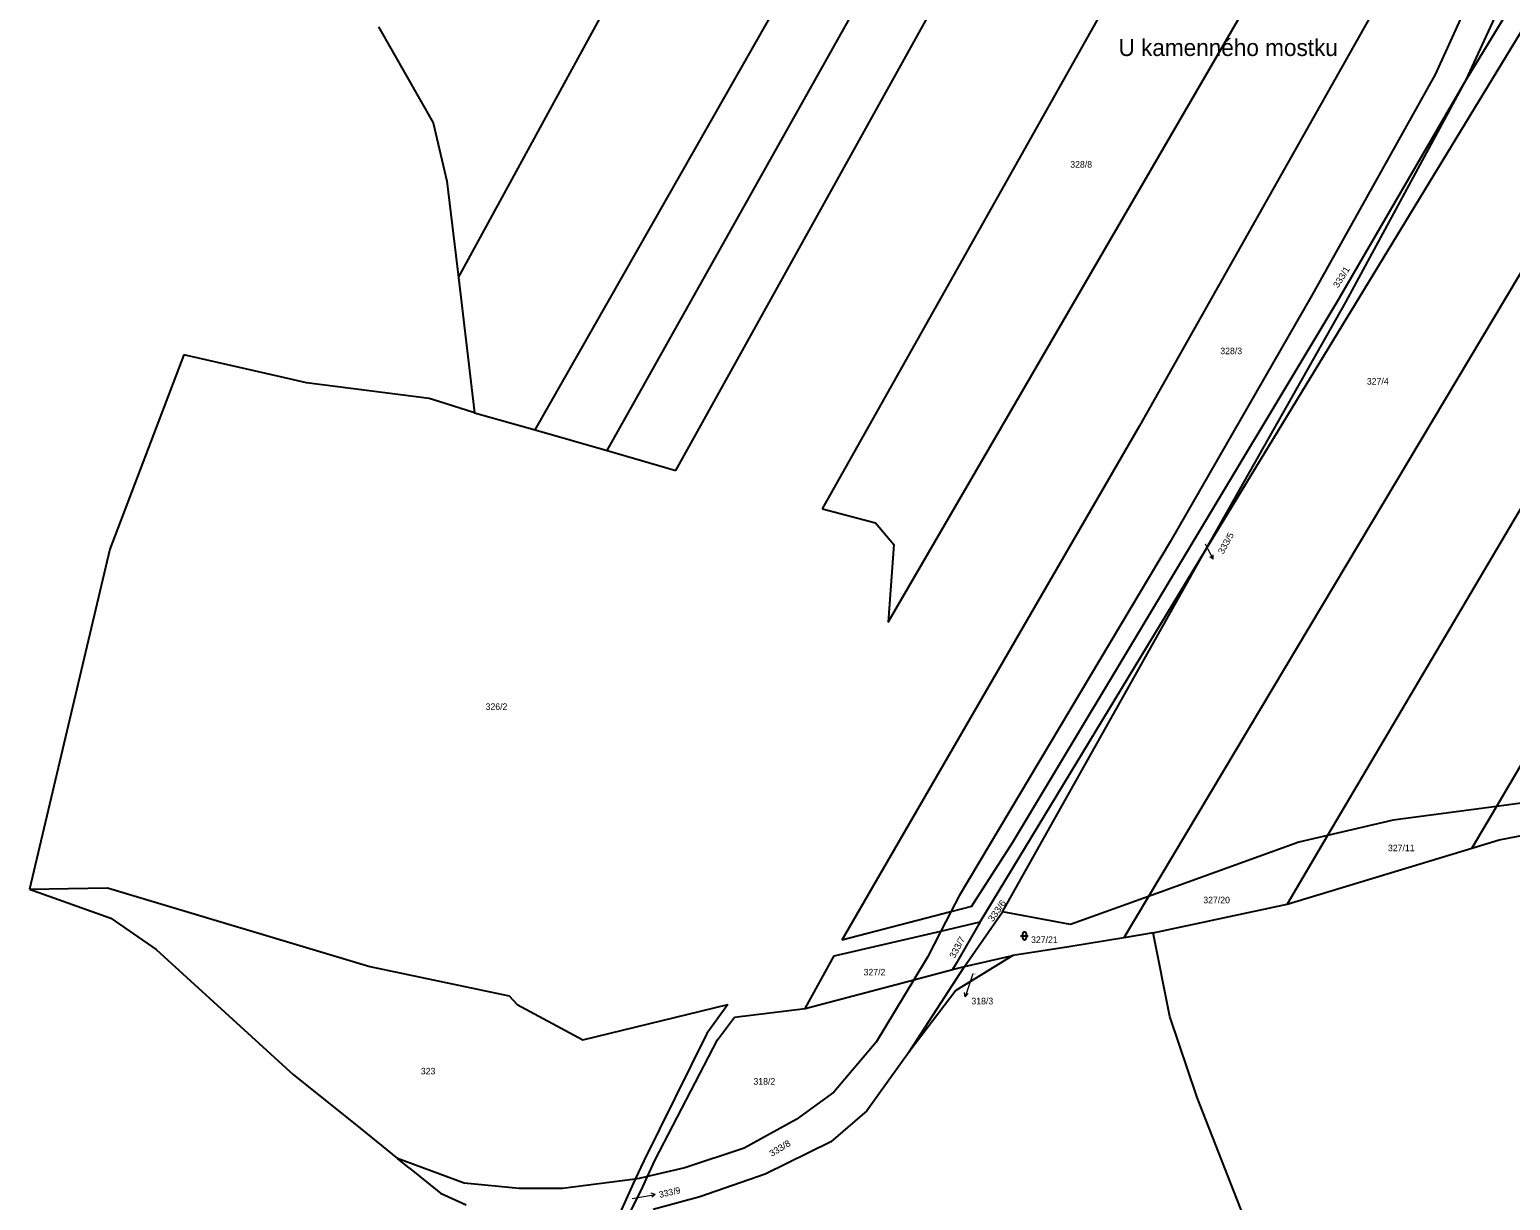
# Model space of a CAD drawing. Extents: x -645290 to -643454, y -1064771 to -1062356.
# Drawn here: x -645018.5 to -644632.1, y -1064454.7 to -1064149.2 of the extents above; entities that cross this region are included whole.
import ezdxf
from ezdxf.enums import TextEntityAlignment as Align

# ---------------------------------------------------------------- set-up
doc = ezdxf.new("R2010")
doc.units = 0
doc.header["$LTSCALE"] = 0.68
for name, color, linetype, lineweight in [('1', 7, 'Continuous', 25), ('3', 7, 'Continuous', 25), ('7', 7, 'Continuous', 13)]:
    doc.layers.add(name, color=color, linetype=linetype, lineweight=lineweight)
doc.layers.add('2', color=7, linetype='Continuous')

msp = doc.modelspace()

# ---------------------------------------------------------------- linework, layer by layer
at = {"layer": '1'}
for p, q in [((-644906.52, -1064213.87), (-644783.89, -1063988.5)), ((-644886.54, -1064253.68), (-644757.8, -1064027.45)), ((-644867.77, -1064259.04), (-644738.28, -1064028.29)), ((-644849.89, -1064264.24), (-644718.76, -1064028.29)), ((-644811.6, -1064274.24), (-644680.91, -1064041.96)), ((-644794.48, -1064303.81), (-644654.09, -1064062.28)), ((-644633.09, -1064082.79), (-644728.84, -1064252.56)), ((-644566.05, -1064106.42), (-644726.5, -1064375.38)), ((-644643.64, -1064162.33), (-644616.86, -1064118.44)), ((-644711.6, -1064285.03), (-644613.22, -1064123.4)), ((-644542.91, -1064127.64), (-644679.8, -1064359.5)), ((-644640.85, -1064137.12), (-644651.74, -1064160.97)), ((-644643.64, -1064162.33), (-644632.24, -1064137.78)), ((-644927.45, -1064148.47), (-644913.14, -1064173.54)), ((-644517.28, -1064150.01), (-644635.73, -1064351.92)), ((-644651.74, -1064160.97), (-644683.79, -1064218.41)), ((-644677.23, -1064220.22), (-644643.64, -1064162.33)), ((-644675.04, -1064220.36), (-644643.64, -1064162.33)), ((-644913.14, -1064173.54), (-644909.57, -1064188.75)), ((-644909.57, -1064188.75), (-644906.52, -1064213.87)), ((-644906.52, -1064213.87), (-644902.35, -1064249.17)), ((-644683.79, -1064218.41), (-644720.83, -1064282.9)), ((-644761.87, -1064361.2), (-644677.23, -1064220.22)), ((-644711.6, -1064285.03), (-644675.04, -1064220.36)), ((-644978.2, -1064234.1), (-644997.51, -1064284.77)), ((-644953.05, -1064239.85), (-644978.2, -1064234.1)), ((-644946.22, -1064241.41), (-644953.05, -1064239.85)), ((-644914.25, -1064245.46), (-644946.22, -1064241.41)), ((-644911.67, -1064246.25), (-644914.25, -1064245.46)), ((-644902.35, -1064249.17), (-644911.67, -1064246.25)), ((-644902.35, -1064249.17), (-644886.54, -1064253.68)), ((-644728.84, -1064252.56), (-644806.55, -1064386.79)), ((-644886.54, -1064253.68), (-644867.77, -1064259.04)), ((-644867.77, -1064259.04), (-644849.89, -1064264.24)), ((-644811.6, -1064274.24), (-644797.78, -1064277.9)), ((-644797.78, -1064277.9), (-644792.98, -1064283.53)), ((-644792.98, -1064283.53), (-644794.48, -1064303.81)), ((-644720.83, -1064282.9), (-644775.91, -1064375.21)), ((-644997.51, -1064284.77), (-645018.48, -1064373.48)), ((-644770.4, -1064382.02), (-644711.6, -1064285.03)), ((-644764.58, -1064379.41), (-644711.6, -1064285.03)), ((-644635.73, -1064351.92), (-644662.62, -1064355.51)), ((-644635.73, -1064351.92), (-644642.1, -1064362.78)), ((-644627.97, -1064350.89), (-644635.73, -1064351.92)), ((-644662.62, -1064355.51), (-644679.8, -1064359.5)), ((-644635.04, -1064360.64), (-644610.32, -1064355.76)), ((-644772.68, -1064377.95), (-644761.87, -1064361.2)), ((-644687.24, -1064361.23), (-644726.5, -1064375.38)), ((-644679.8, -1064359.5), (-644690.36, -1064377.39)), ((-644679.8, -1064359.5), (-644687.24, -1064361.23)), ((-644642.1, -1064362.78), (-644635.04, -1064360.64)), ((-644690.36, -1064377.39), (-644642.1, -1064362.78)), ((-645018.48, -1064373.48), (-644998.19, -1064373.1)), ((-644998.19, -1064373.1), (-644929.72, -1064393.66)), ((-645018.48, -1064373.48), (-644997.3, -1064381.02)), ((-644775.91, -1064375.21), (-644778.06, -1064379.35)), ((-644726.5, -1064375.38), (-644746.85, -1064382.72)), ((-644726.5, -1064375.38), (-644732.91, -1064386.13)), ((-644778.06, -1064379.35), (-644806.55, -1064386.79)), ((-644778.06, -1064379.35), (-644780.67, -1064384.39)), ((-644772.68, -1064377.95), (-644778.06, -1064379.35)), ((-644774.56, -1064393.62), (-644764.58, -1064379.41)), ((-644746.85, -1064382.72), (-644764.58, -1064379.41)), ((-644725.25, -1064384.85), (-644690.36, -1064377.39)), ((-644997.3, -1064381.02), (-644985.45, -1064389.22)), ((-644808.52, -1064390.83), (-644780.67, -1064384.39)), ((-644780.67, -1064384.39), (-644784.21, -1064391.22)), ((-644780.67, -1064384.39), (-644770.4, -1064382.02)), ((-644770.4, -1064382.02), (-644776.94, -1064393.3)), ((-644747.33, -1064388.55), (-644761.89, -1064390.79)), ((-644732.91, -1064386.13), (-644747.33, -1064388.55)), ((-644725.25, -1064384.85), (-644732.91, -1064386.13)), ((-644720.96, -1064406.66), (-644725.25, -1064384.85)), ((-644985.45, -1064389.22), (-644949.61, -1064421.91)), ((-644816.08, -1064404.6), (-644808.52, -1064390.83)), ((-644784.21, -1064391.22), (-644787.76, -1064397.11)), ((-644761.89, -1064390.79), (-644776.79, -1064399.91)), ((-644774.56, -1064393.62), (-644761.89, -1064390.79)), ((-644929.72, -1064393.66), (-644893.37, -1064401.26)), ((-644788.97, -1064415.93), (-644774.56, -1064393.62)), ((-644787.76, -1064397.11), (-644777.68, -1064394.45)), ((-644776.94, -1064393.3), (-644777.68, -1064394.45)), ((-644777.68, -1064394.45), (-644774.56, -1064393.62)), ((-644816.08, -1064404.6), (-644787.76, -1064397.11)), ((-644787.76, -1064397.11), (-644797.53, -1064413.35)), ((-644776.79, -1064399.91), (-644788.97, -1064415.93)), ((-644893.37, -1064401.26), (-644891.27, -1064403.52)), ((-644891.27, -1064403.52), (-644874.15, -1064412.81)), ((-644874.15, -1064412.81), (-644836.31, -1064403.52)), ((-644836.31, -1064403.52), (-644841.72, -1064411.12)), ((-644839.01, -1064412.81), (-644834.51, -1064406.89)), ((-644834.51, -1064406.89), (-644816.08, -1064404.6)), ((-644713.81, -1064427.79), (-644720.96, -1064406.66)), ((-644841.72, -1064411.12), (-644858.24, -1064444.35)), ((-644855.23, -1064444.06), (-644839.01, -1064412.81)), ((-644797.53, -1064413.35), (-644808.62, -1064426.46)), ((-644788.97, -1064415.93), (-644800.01, -1064431.32)), ((-644949.61, -1064421.91), (-644933.65, -1064434.67)), ((-644808.62, -1064426.46), (-644818.45, -1064433.58)), ((-644700.13, -1064462.71), (-644713.81, -1064427.79)), ((-644933.65, -1064434.67), (-644922.5, -1064443.69)), ((-644818.45, -1064433.58), (-644832.06, -1064441)), ((-644800.01, -1064431.32), (-644809.36, -1064439.35)), ((-644832.06, -1064441), (-644847.52, -1064446.17)), ((-644809.36, -1064439.35), (-644826.55, -1064447.8)), ((-644919.32, -1064446.26), (-644922.5, -1064443.69)), ((-644905.1, -1064450.2), (-644922.5, -1064443.69)), ((-644919.32, -1064446.26), (-644911.29, -1064452.76)), ((-644858.24, -1064444.35), (-644860.43, -1064449.12)), ((-644857.23, -1064448.47), (-644855.23, -1064444.06)), ((-644847.52, -1064446.17), (-644857.23, -1064448.47)), ((-644890.74, -1064451.57), (-644905.1, -1064450.2)), ((-644860.43, -1064449.12), (-644879.45, -1064451.57)), ((-644860.43, -1064449.12), (-644864.48, -1064457.95)), ((-644859.43, -1064448.99), (-644860.43, -1064449.12)), ((-644857.23, -1064448.47), (-644859.43, -1064448.99)), ((-644858.45, -1064451.16), (-644857.23, -1064448.47)), ((-644826.55, -1064447.8), (-644843.56, -1064453.69)), ((-644911.29, -1064452.76), (-644904.59, -1064455.83)), ((-644879.45, -1064451.57), (-644890.74, -1064451.57)), ((-644861.67, -1064457.65), (-644858.45, -1064451.16)), ((-644843.56, -1064453.69), (-644855.74, -1064457.02))]:
    msp.add_line(p, q, dxfattribs=at)
at = {"layer": '3'}
for p, q in [((-644759.881, -1064385.651), (-644757.879, -1064385.651)), ((-644759.381, -1064385.151), (-644759.381, -1064386.152)), ((-644758.379, -1064386.152), (-644758.379, -1064385.151))]:
    msp.add_line(p, q, dxfattribs=at)
for centre, start, end in [((-644758.88, -1064385.1509), 0, 180), ((-644758.88, -1064386.1509), 180, 359.98789)]:
    msp.add_arc(centre, 0.5, start, end, dxfattribs=at)
at = {"layer": '7'}
for p, q in [((-644709.591, -1064287.39), (-644709.619, -1064286.27)), ((-644774.327, -1064401.514), (-644773.542, -1064400.716)), ((-644855.255, -1064453.109), (-644856.328, -1064452.79))]:
    msp.add_line(p, q, dxfattribs=at)
for points in [[(-644711.7, -1064283.4), (-644711, -1064284.74), (-644709.591, -1064287.39), (-644710.503, -1064286.741)], [(-644772.38, -1064395.6), (-644773.4, -1064398.66), (-644774.327, -1064401.514), (-644774.494, -1064400.407)], [(-644861.24, -1064454.18), (-644858.21, -1064453.63), (-644855.255, -1064453.109), (-644856.154, -1064453.776)]]:
    msp.add_lwpolyline(points, dxfattribs=at)

# ---------------------------------------------------------------- texts
at = {"layer": '2'}
for s, height, p in [('328/8', 1.7, (-644746.92, -1064185.245)), ('328/3', 1.7, (-644707.77, -1064233.905)), ('327/4', 1.7, (-644669.52, -1064241.834)), ('333/5', 0.2, (-644711.7, -1064283.449)), ('326/2', 1.7, (-644899.49, -1064326.705)), ('327/11', 1.7, (-644664.02, -1064363.564)), ('327/20', 1.7, (-644712.21, -1064377.145)), ('327/21', 1.7, (-644757.15, -1064387.495)), ('327/2', 1.7, (-644800.86, -1064395.965)), ('318/3', 0.2, (-644772.38, -1064395.65)), ('323', 1.7, (-644916.39, -1064421.785)), ('318/2', 1.7, (-644829.6, -1064424.465)), ('333/9', 0.2, (-644861.24, -1064454.229))]:
    msp.add_text(s, height=height, dxfattribs=at).set_placement(p)
for s, rotation, width, p in [('333/1', 58, 1.05, (-644677.029, -1064216.775)), ('333/6', 55, 1.1, (-644767.151, -1064382.153)), ('333/7', 62, 1.05, (-644777.094, -1064391.699)), ('333/8', 31, 1.05, (-644824.831, -1064443.334))]:
    msp.add_text(s, height=1.7, rotation=rotation, dxfattribs=dict(at, width=width)).set_placement(p)
at = {"layer": '2', "width": 1.05}
msp.add_text('333/5', height=1.7, rotation=61, dxfattribs=at).set_placement((-644704.1234, -1064281.0032), align=Align.RIGHT)
at = {"layer": '2'}
msp.add_text('318/3', height=1.7, dxfattribs=at).set_placement((-644767.03, -1064403.515), align=Align.RIGHT)
msp.add_text('333/9', height=1.7, rotation=13, dxfattribs=at).set_placement((-644854.052, -1064454.029))
at = {"layer": '7'}
msp.add_text('U kamenného mostku', height=4.4, dxfattribs=at).set_placement((-644705.71, -1064156.12), align=Align.CENTER)

doc.saveas('drawing.dxf')
